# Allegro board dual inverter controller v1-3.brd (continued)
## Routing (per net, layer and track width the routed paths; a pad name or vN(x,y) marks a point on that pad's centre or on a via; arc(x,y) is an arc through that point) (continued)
1: length 124.9
  TOP w0.381: DT9.3 v1(220.56,97.14) ; LT27.2 220.22,103.26 CT154.2 v1(221.69,103.12) ; UT38.15 214.77,99.37 215.22,99.82 CT155.2 CT151.2 v1(218.69,99.82) ; UT38.11 214.36,94.29 214.74,93.91 v1(214.74,93.63) 215.08,93.29 RT228.2
  GND1 w0.381: JT3.11 231.36,112.5 ; JT3.11 228.85,115.02 ; JT3.11 226.99,114.36 ; JT3.11 228.85,109.99 ; JT3.11 226.33,112.5 ; JT3.11 230.7,114.36 ; JT3.11 230.7,110.65 ; JT3.11 226.99,110.65 ; 226.99,85.66 JT3.10 ; JT3.10 228.85,90.03 ; JT3.10 230.7,89.37 ; JT3.10 226.33,87.51 ; JT3.10 228.85,85 ; JT3.10 231.36,87.51 ; JT3.10 226.99,89.37 ; JT3.10 230.7,85.66 ; JT3.3 228.14,99.29 ; JT3.3 226.71,99.29 ; JT3.3 227.43,99.11 ; JT3.3 228.33,100.01 ; JT3.3 226.71,100.72 ; JT3.3 227.43,100.91 ; JT3.3 228.14,100.72 ; JT3.3 226.52,100.01 ; 227.43,104.65 JT3.5 ; JT3.5 228.14,106.26 ; JT3.5 228.14,104.83 ; JT3.5 227.43,106.45 ; JT3.5 228.33,105.55 ; JT3.5 226.71,106.26 ; JT3.5 226.71,104.83 ; JT3.5 226.52,105.55
  PWR2 w0.381: JT3.11 230.7,110.65 ; JT3.11 226.33,112.5 ; JT3.11 226.99,110.65 ; JT3.11 231.36,112.5 ; JT3.11 228.85,109.99 ; JT3.11 230.7,114.36 ; JT3.11 228.85,115.02 ; JT3.11 226.99,114.36 ; JT3.10 231.36,87.51 ; JT3.10 228.85,90.03 ; JT3.10 226.99,85.66 ; JT3.10 226.99,89.37 ; JT3.10 230.7,89.37 ; JT3.10 226.33,87.51 ; JT3.10 230.7,85.66 ; JT3.10 228.85,85 ; 227.43,104.65 JT3.5 ; JT3.5 228.33,105.55 ; JT3.5 226.71,106.26 ; JT3.5 227.43,106.45 ; JT3.5 228.14,106.26 ; JT3.5 226.52,105.55 ; JT3.5 228.14,104.83 ; JT3.5 226.71,104.83 ; JT3.3 228.33,100.01 ; JT3.3 226.71,99.29 ; JT3.3 226.52,100.01 ; JT3.3 227.43,100.91 ; JT3.3 226.71,100.72 ; JT3.3 228.14,100.72 ; JT3.3 228.14,99.29 ; JT3.3 227.43,99.11
CANA-H: length 18
  TOP w0.381: JT3.7 226.65,98.62 225.44,97.4 222.46,97.4 221.79,98.08 DT9.1 218.18,98.08 RT224.1 217.23,97.94 216.71,97.42 216.17,97.42 215.84,97.75 215.1,97.75 214.74,98.1 UT38.14
CANA-L: length 14.9
  TOP w0.381: JT3.2 226.28,97.24 225.89,96.85 222.46,96.85 221.82,96.2 DT9.2 218.18,96.2 RT224.2 217.23,96.34 216.71,96.86 215.94,96.86 215.61,97.19 215.1,97.19 214.74,96.83 UT38.13
CANA-RX: length 109.9
  TOP w0.381: v1(172.04,102.97) 171.6,102.53 171.6,100.78 121.24,50.43 121.24,49.34 120.83,48.92 JT26.80 ; UT38.5 197.16,100.64 194.65,103.16 190.18,103.16 190.17,103.17 v1(189.35,103.17)
  BOTTOM w0.381: v1(172.04,102.97) 172.24,103.17 v1(189.35,103.17)
CANA-TX: length 109.3
  TOP w0.381: v1(172.59,102.41) 172.59,100.96 121.83,50.2 121.83,49.13 121.64,48.94 JT26.82 ; v1(189.35,102.38) 190.17,102.38 190.18,102.4 194.35,102.4 198.64,98.1 UT38.7
  BOTTOM w0.381: v1(172.59,102.41) 188.65,102.41 188.68,102.38 v1(189.35,102.38)
CASE-TEMP: length 58.3
  TOP w0.381: JT26.30 97.64,50.31 92.44,55.51 90.92,55.51 87.28,59.14 v1(86.19,59.14)
  LAYER3 w0.381: v1(77.12,91.73) 77.12,76.82 81.34,72.6 81.34,64.61 86.19,59.76 v1(86.19,59.14)
  BOTTOM w0.381: RB26.2 CB11.1 77.12,92.45 77.12,92.45 v1(77.12,91.73)
COS-A: length 111.5
  TOP w0.381: JT26.36 100.02,54.48 101.73,56.19 v1(103.09,56.19) ; CT54.1 JT20.1
  TOP w0.508: CT54.1 RT99.2
  LAYER3 w0.381: JT20.1 187.57,70.2 184.31,66.94 184.31,62.49 178.01,56.19 v1(103.09,56.19)
COS-A-N: length 23.8
  TOP w0.381: JT18.6 225.39,74.66 224.22,74.66 220.13,70.57 218.14,70.57 217.17,69.6 215.24,69.6 214.64,70.2 DT13.3 213.9,70.2 213.87,70.18 213.32,70.18 212.92,70.57 210.04,70.57 209.52,70.05 RT95.1
  TOP w0.508: RT95.1 CT53.1 207.16,70.07 RT96.1
COS-A-P: length 23.8
  TOP w0.381: JT18.5 225.24,75.22 223.99,75.22 219.9,71.13 218.2,71.13 217.81,71.52 217.1,71.52 217.08,71.5 DT13.6 215.95,72.11 213.9,72.11 212.92,71.13 210.04,71.13 209.52,71.65 RT95.2
  TOP w0.508: RT93.1 207.1,71.57 CT53.2 RT95.2
COS-B: length 99.9
  TOP w0.381: v1(103.18,54.46) 102.45,53.73 102.45,48.66 102.44,48.65 JT26.42 ; CT72.1 JT27.1
  TOP w0.508: CT72.1 RT121.2
  LAYER3 w0.381: JT27.1 179.38,55.17 178.67,54.45 156.34,54.45 156.19,54.6 103.94,54.6 103.8,54.46 v1(103.18,54.46)
COS-B-N: length 23.2
  TOP w0.381: RT117.1 209.52,55.02 210.04,55.54 212.86,55.54 213.25,55.15 213.87,55.15 213.89,55.17 DT10.3 215.13,55.17 215.69,54.61 217.12,54.61 217.81,55.29 219.33,55.29 222.26,58.23 225.32,58.23 JT22.6
  TOP w0.508: RT119.1 207.16,55.04 CT71.1 RT117.1
COS-B-P: length 23.2
  TOP w0.381: JT22.5 225.32,58.78 222.03,58.78 219.34,56.1 218.19,56.1 217.79,56.49 217.1,56.49 217.08,56.47 DT10.6 216.34,56.47 215.78,57.03 213.79,57.03 212.86,56.1 210.04,56.1 209.52,56.62 RT117.2
  TOP w0.508: RT115.1 207.1,56.54 CT71.2 RT117.2
CURRENT-U: length 90
  TOP w0.381: v1(90.41,48.78) 90.42,48.77 JT26.12 ; JT11.1 127.85,110.63 127.9,110.68 RT50.2
  LAYER3 w0.508: v1(90.41,48.78) 90.41,51.08 100.05,60.71 110.55,60.71 127.85,78.01 JT11.1
  BOTTOM w0.381: CB55.1 87.01,51 88.56,49.45 89.96,49.45 90.41,49 v1(90.41,48.78)
CURRENT-U_N: length 63.8
  TOP w0.381: RT4.2 128.68,123.25 RT14.1
  TOP w0.508: 181.45,136.61 177.33,136.61 176.19,137.75 135.53,137.75 129.13,131.35 129.13,126.21 128.68,125.75 RT4.2
CURRENT-U_P: length 61.9
  TOP w0.381: RT15.1 130.28,123.25 RT4.1
  TOP w0.508: RT4.1 130.28,125.75 129.82,126.21 129.82,131.07 135.81,137.06 175.31,137.06 178.91,133.46 178.91,132.8
CURRENT-V: length 94.3
  TOP w0.381: JT4.1 139.96,110.63 140.02,110.68 RT51.2 ; JT26.14 91.24,48.77 v1(91.23,48.78)
  LAYER3 w0.508: v1(91.23,48.78) 91.23,50.35 100.39,59.51 111.47,59.51 139.96,88 JT4.1
  BOTTOM w0.381: v1(91.23,48.78) 91.23,49.4 90.61,50.02 89.74,50.02 88.76,51 CB56.1
CURRENT-V_N: length 52.4
  TOP w0.381: RT5.2 140.84,123.25 RT16.1
  TOP w0.508: RT5.2 141.49,125.47 141.49,131.54 145.18,135.24 172.56,135.24 173.12,134.68 v1(173.57,134.68)
  BOTTOM w0.508: v1(173.57,134.68) 175.42,136.53 179.41,136.53 180.69,135.25 180.69,134.83 JB1.5
CURRENT-V_P: length 47.6
  TOP w0.381: RT17.1 142.44,123.25 RT5.1
  TOP w0.508: RT5.1 142.12,125.14 142.12,125.16 142.17,125.21 142.17,131.26 145.47,134.55 172.27,134.55 172.63,134.19 v1(172.63,133.74)
  BOTTOM w0.508: v1(172.63,133.74) 174.03,133.74 175.62,135.34 178.91,135.34
CURRENT-W: length 98.7
  TOP w0.381: RT52.2 152.19,110.68 152.16,110.65 JT12.1 ; JT26.18 92.84,48.76 v1(92.83,48.77)
  LAYER3 w0.508: JT12.1 152.16,104.25 142.96,95.06 142.96,88.98 112.2,58.23 100.71,58.23 92.83,50.35 v1(92.83,48.77)
  BOTTOM w0.381: CB57.1 90.51,51 91.87,49.64 92.45,49.64 92.83,49.26 v1(92.83,48.77)
CURRENT-W_N: length 33.9
  TOP w0.381: RT18.1 153.01,123.25 RT6.2
  TOP w0.508: JB1.7 178.77,131.53 178.69,131.61 158.22,131.61 153.5,126.89 153.5,125.31 RT6.2
CURRENT-W_P: length 30.5
  TOP w0.381: RT6.1 154.61,123.25 RT19.1
  TOP w0.508: RT6.1 154.19,125.25 154.19,126.6 158.51,130.92 178.41,130.92 178.91,130.41 178.91,130.25
CURRENT-X: length 65.7
  TOP w0.381: JT26.26 96.04,48.76 v1(96.03,48.77)
  TOP w0.508: RT171.2 JT40.1
  LAYER3 w0.508: v1(96.03,48.77) 96.03,48.08 96.88,47.23 106.92,47.23 113.03,41.12 120.17,41.12 120.91,40.37 126.5,40.37 127.52,39.35 143.32,39.35 145.95,36.72 JT40.1
  BOTTOM w0.381: v1(96.03,48.77) 96.03,49.93 95.75,50.21 CB60.1
CURRENT-X_N: length 43.4
  TOP w0.381: JB5.7 153.65,7.12 147.12,13.66 RT213.2 147.12,19.92 RT210.1
CURRENT-X_P: length 42.9
  TOP w0.381: 178.91,5.86 177.76,5.86 177.05,6.57 153.42,6.57 146.56,13.43 146.56,17.46 146.54,17.48 146.52,17.48 146.3,17.69 146.3,18.23 146.18,18.35 RT213.1 145.52,19.92 RT209.1
CURRENT-Y: length 55.4
  TOP w0.381: v1(95.21,48.77) 95.22,48.75 JT26.24
  TOP w0.508: RT170.2 JT39.1
  LAYER3 w0.508: JT39.1 128.75,36.72 126.12,39.35 120.66,39.35 119.66,40.35 112.53,40.35 106.55,46.34 95.77,46.34 95.21,46.9 v1(95.21,48.77)
  BOTTOM w0.381: v1(95.21,48.77) 95.21,49.81 94.02,51 CB59.1
CURRENT-Y_N: length 61.9
  TOP w0.381: RT208.1 134.95,19.92 RT212.2 134.95,16.17 136.79,14.33 138.44,14.33 148.73,4.05 180.6,4.05 183.14,6.59 183.14,7.97 JB5.5
CURRENT-Y_P: length 68.5
  TOP w0.381: RT207.1 133.35,19.92 RT212.1 133.48,18.35 134.35,17.48 134.39,17.48 134.39,15.94 136.56,13.78 138.21,13.78 148.5,3.49 180.84,3.49 183.7,6.36 183.7,9.01 181.78,10.94 178.91,10.94
CURRENT-Z: length 44.7
  TOP w0.381: v1(93.62,48.77) 93.62,48.76 JT26.20
  TOP w0.508: RT169.2 JT38.1
  LAYER3 w0.508: v1(93.62,48.77) 93.62,47.22 95.39,45.45 106.2,45.45 107.16,44.48 107.16,44.47 112.04,39.59 118.52,39.59 121.39,36.72 JT38.1
  BOTTOM w0.381: CB58.1 92.27,51 93.62,49.65 v1(93.62,48.77)
CURRENT-Z_N: length 63.7
  TOP w0.381: v1(136.53,12.02) 136.19,11.67 130.09,11.67 123.86,17.89 123.16,17.89 122.78,18.27 RT211.2 122.78,19.92 RT206.1
  BOTTOM w0.381: JB5.3 178.86,12.2 178.83,12.17 176.03,12.17 175.52,11.67 136.88,11.67 v1(136.53,12.02)
CURRENT-Z_P: length 63.9
  TOP w0.381: v1(136.53,10.76) 136.19,11.11 129.85,11.11 123.63,17.33 122.93,17.33 122.78,17.48 122.18,17.48 121.31,18.35 RT211.1 121.18,19.92 RT205.1 ; 178.91,8.48 JB5.6
  BOTTOM w0.381: JB5.6 176.2,11.11 136.88,11.11 v1(136.53,10.76)
EMUI: length 59.3
  TOP w0.381: JT17.14 67.45,88.38 65.95,86.88 65.95,71.47 68,69.43 74.08,69.43 75.23,68.28 75.23,65.07 77.71,62.59 77.71,51.54 79.86,49.39 84.26,49.39 85.33,48.32 85.33,46.19 85.87,45.65 JT26.1
EMUO: length 58.6
  TOP w0.381: JT26.2 86.44,48.65 85.07,50.02 80.12,50.02 78.34,51.8 78.34,62.85 75.86,65.33 75.86,68.54 74.34,70.06 68.26,70.06 66.58,71.74 66.58,86.34 67.4,87.16 69.78,87.16 JT17.13
EXC-A-N: length 60.5
  TOP w0.254: CT158.2 RT233.2 216.26,36.21 UT41.9
  TOP w0.381: DT15.3 238.5,74.43 237.42,74.43 236.9,74.95 232.59,74.95 JT18.2 ; CT158.2 219.35,36 v1(219.6,36.25)
  LAYER3 w0.381: JT18.2 231.39,72.57 234.5,69.46 234.5,56.83 228.26,50.59 223.96,50.59 221.86,48.49 221.86,40.23 220.24,38.61 220.24,36.89 v1(219.6,36.25)
EXC-A-P: length 63.1
  TOP w0.254: CT157.2 RT230.2 216.27,38.81 UT41.13
  TOP w0.381: JT18.1 232.16,75.51 237.16,75.51 237.96,76.31 240.1,76.31 DT15.6 ; CT157.2 219.36,39.02 v1(219.6,39.26)
  LAYER3 w0.381: JT18.1 230.13,75.03 230.13,73.04 233.94,69.23 233.94,57.06 228.03,51.15 223.73,51.15 221.3,48.72 221.3,40.46 220.1,39.26 v1(219.6,39.26)
EXC-B-N: length 32.1
  TOP w0.254: CT166.2 RT244.2 216.47,44.87 UT43.9
  TOP w0.381: v1(219.73,44.67) CT166.2 ; JT22.2 232.53,57.23 233.52,58.23 236.64,58.23 237.09,57.77 238.11,57.77 238.13,57.79 DT12.3
  LAYER3 w0.381: JT22.2 231.39,56.81 226.55,51.97 223.03,51.97 220.57,49.51 220.57,45.51 v1(219.73,44.67)
EXC-B-P: length 34.1
  TOP w0.254: UT43.13 216.47,47.47 RT237.2 CT162.2
  TOP w0.381: JT22.1 232.53,59.77 233.52,58.78 236.58,58.78 237.45,59.65 239.73,59.65 240.29,59.09 DT12.6 ; CT162.2 219.61,47.69 v1(219.9,47.97)
  LAYER3 w0.381: v1(219.9,47.97) 219.88,47.99 219.88,49.62 222.79,52.53 226.32,52.53 230.14,56.35 230.14,58.53 JT22.1
GLOBAL-FAULT-ALL: length 64.5
  TOP w0.381: v1(160.72,59.19) 161.66,59.19 162.7,58.14 JT26.134 ; v1(168.16,78.19) 168.16,80.5 173.82,86.17 185.25,86.17 187.46,83.96 JT16.1
  LAYER3 w0.381: v1(168.16,78.19) 168.16,66.01 161.34,59.19 v1(160.72,59.19)
  BOTTOM w0.381: UB17.4 159.6,60.31 v1(160.72,59.19)
GLOBAL-FAULT-UVW: length 22.7
  TOP w0.381: JT26.130 v1(161.1,57.69)
  BOTTOM w0.381: UB15.4 159.6,63.76 ; 159.6,63.76 160.13,64.29 161.76,64.29 162.8,63.25 162.8,59.38 v1(161.1,57.69) ; 159.6,63.76 UB17.3
GLOBAL-FAULT-XYZ: length 26.4
  TOP w0.381: JT26.132 161.91,47.67 v1(161.91,48.83) 161.91,57.98 161.53,58.36 v1(160.59,58.36)
  BOTTOM w0.381: UB17.6 157.69,59.99 159.32,58.36 v1(160.59,58.36) ; UB20.4 159.06,40.69 159.8,41.42 159.8,46.72 v1(161.91,48.83)
I2CA-SCL: length 91.2
  TOP w0.381: v1(124.03,44.4) JT26.87 ; v1(124,49.2) 124,50.01 175.51,101.52 175.51,106 175.64,106.12 RT54.1 175.64,107.76 175.3,108.1 JT2.9
  BOTTOM w0.381: v1(124.03,44.4) 124.03,45.02 124,45.05 v1(124,49.2)
I2CA-SDA: length 93.9
  TOP w0.381: v1(123.29,49.6) 123.29,50.22 172.88,99.82 173.02,99.82 173.5,100.3 RT53.1 173.5,107.95 174.04,108.48 174.04,114.12 JT2.10 ; JT26.85 v1(123.24,44.4)
  BOTTOM w0.381: v1(123.29,49.6) 123.24,49.55 v1(123.24,44.4)
LED-G: length 20
  TOP w0.381: v1(163.61,43.39) 162.7,44.3 JT26.133 ; RT154.1 v1(178.34,39.51)
  BOTTOM w0.381: v1(163.61,43.39) 165.32,41.69 176.15,41.69 v1(178.34,39.51)
LED-R: length 16.5
  TOP w0.381: RT152.1 v1(172.88,39.51) ; JT26.129 161.1,43.64 v1(162.48,42.26)
  BOTTOM w0.381: v1(162.48,42.26) 164.65,40.09 172.29,40.09 v1(172.88,39.51)
LED-Y: length 18.3
  TOP w0.381: JT26.131 161.92,43.98 v1(163.06,42.84) ; RT153.1 v1(175.61,39.51)
  BOTTOM w0.381: v1(175.61,39.51) 174.21,40.9 164.99,40.9 v1(163.06,42.84)
PWM7A: length 116.5
  TOP w0.381: JT26.58 112.04,54.17 119.14,61.27 124.28,61.27 160.46,97.45 160.46,116.72 164.65,120.91 v1(177.28,120.91)
  LAYER3 w0.381: v1(177.28,120.91) 177.84,120.35 JT2.12
PWM7B: length 116.5
  TOP w0.381: v1(176.57,119.92) 175.94,119.92 175.59,120.28 164.92,120.28 161.09,116.46 161.09,97.19 124.55,60.64 119.62,60.64 112.83,53.85 JT26.60
  LAYER3 w0.381: JT2.11 176.58,114.09 176.58,119.03 176.57,119.05 v1(176.57,119.92)
PWM8A: length 113.7
  TOP w0.381: JT2.14 180.38,117.31 178.66,119.02 164.56,119.02 161.73,116.19 161.73,96.92 124.78,59.98 120.11,59.98 113.64,53.51 JT26.62
PWM8B: length 113.9
  TOP w0.381: JT26.64 114.43,53.22 120.48,59.28 124.98,59.28 162.36,96.66 162.36,115.93 164.82,118.39 177.94,118.39 179.09,117.24 179.09,114.12 JT2.13
PWM9A: length 55.2
  TOP w0.381: RT66.1 v1(183.54,93.72) ; v1(176.32,50.12) 176.32,74.46 182.25,80.4 v1(182.28,80.4) ; JT26.167 v1(176.32,44.29)
  BOTTOM w0.381: v1(183.54,93.72) 182.28,92.46 v1(182.28,80.4) ; v1(176.32,50.12) v1(176.32,44.29)
PWM9B: length 44.7
  TOP w0.381: RT75.1 184.13,87.85 183.96,87.69 v1(183.3,87.69) ; JT26.168 176.32,49.01 177.07,49.77 177.07,74.02 182.74,79.69 182.84,79.69 v1(183.3,80.15)
  BOTTOM w0.381: v1(183.3,80.15) v1(183.3,87.69)
QEA_A: length 71.5
  TOP w0.381: v1(119.4,51.45) 118.76,50.81 118.35,50.81 118.35,50.81 117.64,50.81 116.03,49.2 JT26.68
  BOTTOM w0.381: UB22.3 169.97,31.11 167.49,33.58 155.74,33.58 149.18,40.14 123.63,40.14 119.03,44.74 119.03,51.09 v1(119.4,51.45)
QEA_B: length 68.9
  TOP w0.381: v1(119.9,50.63) 119.27,50 117.98,50 116.84,48.86 JT26.70
  BOTTOM w0.381: v1(119.9,50.63) 119.9,50.25 119.71,50.06 119.71,50.05 119.59,49.92 119.59,44.97 123.86,40.7 149.41,40.7 155.88,34.23 167.76,34.23 170.24,31.76 UB22.4
QEA_I: length 65.4
  TOP w0.381: JT26.74 118.44,48.65 118.93,49.14 119.75,49.14 v1(120.39,49.78)
  BOTTOM w0.381: UB22.5 170.5,32.41 168.03,34.88 156.02,34.88 149.64,41.26 124.1,41.26 120.15,45.2 120.15,48.92 120.39,49.16 v1(120.39,49.78)
QEB_A: length 56.5
  TOP w0.381: v1(147.58,50.78) 131.02,50.78 128.83,48.59 JT26.100
  BOTTOM w0.381: v1(147.58,50.78) 147.58,44.11 156.16,35.53 168.3,35.53 170.77,33.06 UB22.6
QEB_B: length 54.2
  TOP w0.381: JT26.102 129.64,48.32 131.43,50.11 v1(148.26,50.11)
  BOTTOM w0.381: UB22.7 171.04,33.71 168.57,36.18 156.41,36.18 148.22,44.37 148.22,49.4 148.26,49.44 v1(148.26,50.11)
QEB_I: length 51.4
  TOP w0.381: v1(148.93,49.44) 133.92,49.44 133.91,49.45 132.04,49.45 131.24,48.65 JT26.106
  BOTTOM w0.381: UB22.8 171.31,34.36 168.84,36.83 156.66,36.83 148.85,44.63 148.85,48.69 148.93,48.76 v1(148.93,49.44)
QEPA-A-IN: length 20.2
  TOP w0.381: RT186.2 CT118.1 191.13,27.53 190.43,26.83 JT41.1
  BOTTOM w0.381: UB22.21 179,31.76 181.32,29.45 181.32,27.24 183.12,25.43 185.25,25.43 JT41.1
QEPA-B-IN: length 20.9
  TOP w0.381: CT131.1 RT194.2 191.15,24.27 191.1,24.21 185.18,24.21 184.11,25.28 JT41.2
  BOTTOM w0.381: UB22.20 179.27,32.41 181.97,29.72 181.97,27.77 182.9,26.83 JT41.2
QEPA-I-IN: length 18.6
  TOP w0.381: JT41.3 190.91,29.37 191.13,29.15 CT116.1 RT172.2
  BOTTOM w0.381: JT41.3 185.39,28.11 183.59,28.11 182.62,29.09 182.62,29.99 179.54,33.06 UB22.19
QEPB-A-IN: length 17
  TOP w0.381: CT106.1 RT166.2 191.15,32.41 190.38,33.18 185.38,33.18 JT41.6
  BOTTOM w0.381: JT41.6 182.61,31.91 180.81,33.71 UB22.18
QEPB-B-IN: length 17
  TOP w0.381: RT156.2 CT99.1 190.58,35.66 189.37,34.45 JT41.7
  BOTTOM w0.381: JT41.7 185.39,33.19 182.25,33.19 181.08,34.36 UB22.17
QEPB-I-IN: length 17.5
  TOP w0.381: CT91.1 RT148.2 191.15,38.91 187.95,35.71 185.37,35.71 JT41.8
  BOTTOM w0.381: JT41.8 181.91,34.45 181.35,35.01 UB22.16
RSLV-A-PWM: length 17
  TOP w0.381: JT26.169 177.1,44.64 178.2,43.54 181.85,43.54 182.48,44.17 188.19,44.17 189.25,45.23 RT163.1
RSLV-B-PWM: length 16.7
  TOP w0.381: JT26.170 177.1,48.68 179.16,50.74 RT242.1
SD-C1: length 91.8
  TOP w0.381: JT2.15 182.92,106.2 129.64,52.93 v1(129.64,52.92) ; JT26.101 v1(129.64,44.38)
  BOTTOM w0.381: v1(129.64,44.38) v1(129.64,52.92)
SD-C2: length 92.2
  TOP w0.381: JT2.17 185.46,106.48 131.24,52.26 v1(131.24,52.25) ; JT26.105 v1(131.24,44.38)
  BOTTOM w0.381: v1(131.24,44.38) v1(131.24,52.25)
SD-C3: length 92.6
  TOP w0.381: JT2.19 188,106.76 132.84,51.6 v1(132.84,51.6) ; JT26.109 v1(132.84,44.38)
  BOTTOM w0.381: v1(132.84,44.38) v1(132.84,51.6)
SD-D1: length 94.7
  TOP w0.381: JT2.16 182.92,114.61 181.66,113.36 181.66,106.09 128.83,53.26 v1(128.83,53.25) ; JT26.99 v1(128.83,44.38)
  BOTTOM w0.381: v1(128.83,44.38) v1(128.83,53.25)
SD-D2: length 95.1
  TOP w0.381: JT26.103 v1(130.43,44.38) ; v1(130.43,52.59) 130.43,52.6 184.2,106.37 184.2,114.12 JT2.18
  BOTTOM w0.381: v1(130.43,44.38) v1(130.43,52.59)
SD-D3: length 95.4
  TOP w0.381: JT26.107 v1(132.03,44.38) ; v1(132.03,51.93) 132.03,51.94 186.74,106.65 186.74,114.12 JT2.20
  BOTTOM w0.381: v1(132.03,44.38) v1(132.03,51.93)
SHUTDOWN+15V: length 59
  TOP w0.381: v1(220.16,34.57) 221.44,34.57 RT160.1 RT161.1 ; JT26.155 171.46,45.6 v1(171.46,44.23)
  LAYER3 w0.381: v1(175.32,42.91) 185.5,42.91 195.8,32.6 218.2,32.6 v1(220.16,34.57)
  BOTTOM w0.381: v1(175.32,42.91) 172.02,42.91 171.46,43.47 v1(171.46,44.23)
SIN-A: length 119.3
  TOP w0.381: CT45.1 JT19.1 ; JT26.34 99.24,54.66 101.55,56.97 v1(103.03,56.97)
  TOP w0.508: CT45.1 RT83.2
  LAYER3 w0.381: JT19.1 187.47,77.71 183.5,73.74 183.5,62.82 177.65,56.97 v1(103.03,56.97)
SIN-A-N: length 27.3
  TOP w0.381: RT80.1 209.52,77.56 210.04,78.09 212.82,78.09 213.22,77.69 214.4,77.69 DT14.3 215.03,77.1 217.22,77.1 218.2,78.09 226.76,78.09 227.58,77.26 227.58,75.01 JT18.4
  TOP w0.508: RT80.1 CT44.1 207.16,77.59 RT81.1
SIN-A-P: length 25.5
  TOP w0.381: RT80.2 209.52,79.16 210.04,78.64 212.84,78.64 213.77,79.57 215.4,79.57 215.96,79.01 DT14.6 217.11,79.01 217.14,79.04 217.69,79.04 218.09,78.64 226.99,78.64 228.85,76.79 JT18.3
  TOP w0.508: RT80.2 CT44.2 207.1,79.09 RT79.1
SIN-B: length 104.2
  TOP w0.381: v1(103.18,55.41) 102.56,55.41 101.62,54.47 JT26.40 ; CT63.1 JT23.1
  TOP w0.508: CT63.1 RT105.2
  LAYER3 w0.381: v1(103.18,55.41) 115.5,55.41 115.52,55.43 178.53,55.43 185.78,62.68 JT23.1
SIN-B-N: length 28.1
  TOP w0.381: RT102.1 209.52,62.53 210.04,63.05 212.78,63.05 213.18,62.66 213.87,62.66 213.9,62.68 DT11.3 214.64,62.68 215.2,62.12 217.23,62.12 218.18,63.08 225.58,63.08 227.5,61.16 227.5,58.58 JT22.4
  TOP w0.508: RT102.1 CT61.1 207.16,62.56 RT103.1
SIN-B-P: length 26.5
  TOP w0.381: JT22.3 228.85,60.61 225.81,63.64 218.12,63.64 217.69,64.07 216.64,64.07 DT11.6 216.55,64.18 216.08,64.65 213.82,64.65 212.78,63.61 210.04,63.61 209.52,64.13 RT102.2
  TOP w0.508: RT102.2 CT61.2 207.1,64.06 RT101.1
SPIA-CLK: length 97.7
  TOP w0.381: JT26.71 v1(117.63,44.38) ; JT2.6 171.47,114.12 171.47,111.3 168.34,108.16 168.34,99.29 121.78,52.73 117.83,52.73 v1(117.26,52.16)
  BOTTOM w0.381: v1(117.26,52.16) 117.26,45.37 117.63,45 v1(117.63,44.38)
SPIA-MISO: length 94.8
  TOP w0.381: JT26.69 v1(116.84,44.38) ; JT2.5 170.22,111.63 167.78,109.19 167.78,99.59 121.53,53.34 116.98,53.34 v1(116.47,52.83)
  BOTTOM w0.381: v1(116.84,44.38) 116.7,44.52 116.7,44.66 116.47,44.89 v1(116.47,52.83)
SPIA-MOSI: length 94.5
  TOP w0.381: JT2.3 167.68,111.41 166.87,110.61 166.87,99.5 121.32,53.94 116.1,53.94 v1(115.66,53.5) ; JT26.67 v1(116.03,44.38)
  BOTTOM w0.381: v1(116.03,44.38) 115.66,44.75 v1(115.66,53.5)
SPIA-STE: length 96
  TOP w0.381: JT26.73 v1(118.44,44.38) ; v1(118.07,51.48) 118.76,52.17 122.01,52.17 168.89,99.06 168.89,99.11 169.04,99.25 v1(169.04,107.81)
  BOTTOM w0.381: JT2.4 168.93,114.12 168.93,109.88 168.98,109.83 168.98,108.48 169.04,108.43 v1(169.04,107.81) ; v1(118.07,51.48) 118.07,45.37 118.44,45 v1(118.44,44.38)
TCK: length 54.6
  TOP w0.381: JT26.5 88.04,44.19 87.46,43.62 84.92,43.62 83.6,44.94 83.6,47 82.46,48.14 79.31,48.14 76.44,51.01 76.44,62.06 73.72,64.78 v1(73.72,68.61)
  BOTTOM w0.381: v1(73.72,68.61) 73.72,74.48 72.67,75.53 72.67,81.63 JT17.9 JT17.11
TDI: length 38.8
  TOP w0.381: JT26.8 88.82,49.44 86.34,51.93 80.91,51.93 80.25,52.59 80.25,63.64 77.77,66.12 77.77,69.29 72.98,74.07 72.6,74.07 JT17.3
TDO: length 46.9
  TOP w0.381: JT26.6 88.04,49.12 85.86,51.29 80.65,51.29 79.61,52.33 79.61,63.38 77.13,65.86 77.13,69.07 74.87,71.33 70.47,71.33 69.68,72.12 69.68,79.43 JT17.7
TMS: length 40.8
  TOP w0.381: v1(74.39,67.45) 74.39,65 77.07,62.32 77.07,51.27 79.54,48.8 83.93,48.8 84.54,48.19 84.54,45.09 85.35,44.28 86.89,44.28 87.22,44.61 JT26.3
  BOTTOM w0.381: v1(74.39,67.45) 73.72,67.45 72.32,68.84 72.32,71.81 JT17.1
TRST: length 38.9
  TOP w0.381: JT17.2 68.46,72.12 69.89,70.7 74.6,70.7 76.5,68.8 76.5,65.6 78.98,63.11 78.98,52.06 80.38,50.66 85.35,50.66 87.22,48.78 JT26.4
U-FAULT: length 112.3
  TOP w0.381: JT26.122 157.9,57.4 157.69,57.61 v1(157.69,70.32) ; v1(103.77,115.5) 103.17,114.91 UT8.3
  LAYER3 w0.381: v1(103.77,115.5) 112.51,115.5 116.39,111.62 116.39,100.9 v1(114.54,99.04)
  BOTTOM w0.381: v1(114.54,99.04) 114.54,96.5 127.63,83.41 145.22,83.41 157.69,70.94 v1(157.69,70.32) UB15.1
U-FAULT-N: length 46
  TOP w0.381: v1(112.03,132.45) 111.95,132.37 111.95,131.81 111.81,131.68 111.81,131.28 111.7,131.17 111.7,115.3 109.34,112.94 108.57,112.94 107.96,112.33 LT12.1
  BOTTOM w0.381: JB4.8 95.4,139.49 95.4,136.65 99.03,133.02 110.97,133.02 111.54,132.45 v1(112.03,132.45)
U-FAULT-N-FILTER: length 5.4
  TOP w0.381: RT49.2 102.58,112.42 101.9,113.09 101.62,113.09 101.1,113.61 UT8.1
  TOP w0.508: RT49.2 CT27.2 105.33,112.42 LT12.2
U-FAULT-P: length 41.8
  TOP w0.381: v1(111.14,131.56) 111.14,115.53 109.11,113.5 108.57,113.5 107.96,114.11 LT9.1
  BOTTOM w0.381: v1(111.14,131.56) 111.14,132.06 110.74,132.46 98.8,132.46 94.11,137.15 JB4.7
U-FAULT-P-FILTER: length 5
  TOP w0.381: RT49.1 102.38,114.26 UT8.2
  TOP w0.508: RT49.1 CT27.1 104.11,114.11 LT9.2
U-LEN: length 129
  LAYER3 w0.381: v1(118.3,124.91) 115.74,124.91 105.36,135.29 100.49,135.29 100.09,134.9 99.07,134.9 98.67,135.29 87.84,135.29 86.49,136.64 JB4.13
  BOTTOM w0.381: UB18.12 165.1,69.98 147.88,87.2 128.91,87.2 118.26,97.84 118.26,123.92 118.3,123.96 v1(118.3,124.91)
U-LEN-OUT: length 11.9
  TOP w0.381: JT26.144 v1(166.72,48.88)
  BOTTOM w0.381: UB18.8 165.75,53.61 166.72,52.64 v1(166.72,48.88)
U-OCEN: length 130.4
  LAYER3 w0.381: JB4.15 83.95,136.63 85.93,134.66 98.52,134.66 98.84,134.34 100.32,134.34 100.64,134.66 105.09,134.66 115.52,124.24 v1(117.63,124.24)
  BOTTOM w0.381: v1(117.63,124.24) 117.63,118.74 117.61,118.73 117.61,97.57 128.64,86.55 147.61,86.55 164.45,69.71 UB18.11
U-OCEN-OUT: length 11.8
  TOP w0.381: JT26.142 v1(165.9,48.88)
  BOTTOM w0.381: UB18.9 165.1,53.34 165.9,52.53 v1(165.9,48.88)
U-PSDIS: length 127.4
  LAYER3 w0.381: v1(118.97,125.58) 115.97,125.58 105.62,135.93 100.33,135.93 99.86,135.45 99.3,135.45 98.83,135.93 90.13,135.93 89.03,137.02 JB4.11
  BOTTOM w0.381: UB18.13 165.75,70.25 148.15,87.85 129.18,87.85 118.89,98.13 118.89,124.54 118.97,124.63 v1(118.97,125.58)
U-PSDIS-OUT: length 12
  TOP w0.381: JT26.146 v1(167.5,48.88)
  BOTTOM w0.381: v1(167.5,48.88) 167.5,52.77 166.4,53.88 UB18.7
U-RTD: length 106
  TOP w0.381: JT26.92 v1(125.63,48.93) ; UT8.5 101.79,116.21 101.8,116.2 102.06,116.2 v1(102.5,115.76) ; v1(86.52,87.51) 87.49,87.51 92.8,82.2 93.71,82.2 102.5,73.41 107.15,73.41 v1(107.99,72.58)
  LAYER3 w0.381: v1(92.64,103.89) 92.64,112.33 94.27,113.95 94.27,114.08 94.65,114.46 95.81,114.46 97.39,116.05 98.84,116.05 99.13,115.76 v1(102.5,115.76)
  BOTTOM w0.254: UB3.2 84.9,90.37 84.51,89.98 84.51,88.78 85.21,88.08 RB32.1
  BOTTOM w0.381: v1(125.63,48.93) 125.63,50.72 107.99,68.36 v1(107.99,72.58) ; RB32.1 85.55,87.56 86.57,87.56 ; v1(86.52,87.51) 86.57,87.56 ; 86.57,87.56 87.92,88.91 87.92,97.39 92.64,102.12 v1(92.64,103.89)
U-RTD-N: length 42.6
  TOP w0.381: LT3.1 107.96,118.8 108.57,118.19 109.11,118.19 109.49,118.58 109.49,136.63 103.65,142.47 92.28,142.47 91.35,141.53 91.35,140.99 JB4.10
U-RTD-N-FILTER: length 5.5
  TOP w0.381: RT32.2 102.58,118.72 101.9,118.04 101.9,117.99 101.42,117.51 UT8.7
  TOP w0.508: LT3.2 104.11,118.8 CT20.2 RT32.2
U-RTD-P: length 48.5
  TOP w0.381: JB4.9 90.32,139.49 90.32,141.29 92.05,143.03 103.88,143.03 110.05,136.86 110.05,118.34 109.34,117.64 108.57,117.64 107.96,117.03 LT6.1
U-RTD-P-FILTER: length 5
  TOP w0.381: UT8.6 102.37,116.86 RT32.1
  TOP w0.508: RT32.1 CT20.1 104.11,117.03 LT6.2
U-TEMP: length 29.5
  TOP w0.381: JT26.25 96.01,45.63 v1(96.01,44.41)
  BOTTOM w0.381: RB66.2 CB48.1 86.22,61.5 90.77,56.96 95.1,56.96 98.54,53.52 98.54,48.34 96.01,45.82 v1(96.01,44.41)
UHS-PWM: length 113
  TOP w0.381: v1(105.64,44.1) JT26.49 ; RT20.1 v1(105.38,122.07) ; v1(93.74,101.08) 93.74,99.98 94.54,99.18 104.03,99.18 117.35,85.87 117.35,73.89 105.64,62.18 v1(105.64,51.06)
  BOTTOM w0.381: v1(93.74,101.08) 93.74,101.7 95.3,103.26 104.49,103.26 107.4,106.17 JT9.1 107.4,110.65 105.38,112.67 v1(105.38,122.07) ; v1(105.64,51.06) v1(105.64,44.1)
UHS-PWM-N: length 26.1
  TOP w0.381: UT1.3 105.33,125.12 106.44,126.22 106.44,131.81 103.52,134.73 100.97,134.73 v1(99.58,136.13)
  BOTTOM w0.381: JB4.4 100.45,139.51 100.45,137.71 99.7,136.96 99.7,136.25 v1(99.58,136.13)
UHS-PWM-P: length 23.8
  TOP w0.381: JB4.3 99.19,137.65 101.06,135.78 103.25,135.78 106.99,132.04 106.99,125.99 105.52,124.51 101.58,124.51 101.54,124.47 UT1.2
ULS-PWM: length 130.5
  TOP w0.381: v1(106.43,51.06) 106.43,61.86 118.13,73.57 118.13,86.2 104.36,99.97 94.9,99.97 94.52,100.35 v1(94.52,101.08) ; RT3.1 103.9,131.17 v1(103.64,131.43) ; v1(106.43,44.1) JT26.51
  BOTTOM w0.381: v1(106.43,51.06) v1(106.43,44.1) ; v1(103.64,131.43) 109.61,125.46 109.61,116.31 113.5,112.43 JT10.1 113.5,106.17 109.8,102.47 95.92,102.47 v1(94.52,101.08)
ULS-PWM-N: length 25.4
  TOP w0.381: UT1.5 102,126.42 102.05,126.46 104.89,126.46 105.85,127.43 105.85,131.6 103.56,133.89 99.2,133.89 97.91,135.18 97.91,139.51 JB4.6
ULS-PWM-P: length 21.7
  TOP w0.381: UT1.6 102,127.07 102.05,127.02 104.66,127.02 105.29,127.66 105.29,131.37 103.33,133.33 98.97,133.33 96.65,135.64 JB4.5
V-FAULT: length 123.7
  TOP w0.381: UT8.11 93.7,116.86 v1(93.23,116.39) ; JT26.124 158.71,57.74 158.7,57.75 158.7,63.74 159.38,64.42 v1(159.38,70.05)
  LAYER3 w0.381: v1(93.23,116.39) 93.9,117.06 112.75,117.06 117.31,112.5 117.31,100.32 115.8,98.81 115.79,98.81 v1(115.35,98.37)
  BOTTOM w0.381: UB15.3 159.6,69.83 v1(159.38,70.05) 145.21,84.22 127.97,84.22 115.35,96.84 v1(115.35,98.37)
V-FAULT-N: length 41.3
  TOP w0.381: JB3.8 65.55,139.49 65.55,135.74 67.35,133.94 81.37,133.94 85.46,129.86 85.46,119.87 86.36,118.96 86.9,118.96 87.51,119.57 LT1.1
V-FAULT-N-FILTER: length 5.4
  TOP w0.381: RT30.2 92.9,119.48 93.83,118.54 93.86,118.54 94.25,118.16 UT8.9
  TOP w0.508: LT1.2 90.14,119.48 CT18.2 RT30.2
V-FAULT-P: length 39.7
  TOP w0.381: JB3.7 64.61,138.23 64.99,137.85 64.99,135.5 67.11,133.38 81.14,133.38 84.9,129.63 84.9,119.63 86.13,118.4 86.9,118.4 87.51,117.79 LT4.1
V-FAULT-P-FILTER: length 5
  TOP w0.381: RT30.1 93.1,117.62 93.54,117.62 93.65,117.51 UT8.10
  TOP w0.508: LT4.2 90.14,117.88 CT18.1 RT30.1
V-LEN: length 159.2
  LAYER3 w0.381: v1(120.24,122.58) 115.38,122.58 104.57,133.39 100.96,133.39 100.78,133.22 82.67,133.22 81.1,134.79 58.5,134.79 56.65,136.64 JB3.13
  BOTTOM w0.381: UB18.15 167.05,70.79 148.69,89.15 129.71,89.15 120.21,98.65 120.21,121.6 120.24,121.62 v1(120.24,122.58)
V-LEN-OUT: length 12.4
  TOP w0.381: JT26.152 v1(169.92,48.88)
  BOTTOM w0.381: v1(169.92,48.88) 169.92,52.23 167.7,54.45 UB18.5
V-OCEN: length 160.7
  LAYER3 w0.381: v1(119.56,121.9) 115.16,121.9 104.31,132.76 101.11,132.76 101.01,132.66 82.33,132.66 80.83,134.15 56.47,134.15 54.11,136.51 JB3.15
  BOTTOM w0.381: UB18.14 166.4,70.52 148.42,88.5 129.45,88.5 119.56,98.38 v1(119.56,121.9)
V-OCEN-OUT: length 12.3
  TOP w0.381: JT26.150 v1(169.1,48.88)
  BOTTOM w0.381: UB18.6 167.05,54.18 169.1,52.12 v1(169.1,48.88)
V-PSDIS: length 157.8
  LAYER3 w0.381: v1(120.91,123.25) 115.61,123.25 104.83,134.03 100.8,134.03 100.55,133.78 98.6,133.78 98.36,134.03 82.76,134.03 81.36,135.42 60.4,135.42 59.19,136.64 JB3.11
  BOTTOM w0.381: UB18.16 167.7,71.06 148.96,89.8 129.98,89.8 120.86,98.92 120.86,122.25 120.91,122.3 v1(120.91,123.25)
V-PSDIS-OUT: length 12.5
  TOP w0.381: JT26.154 v1(170.7,48.88)
  BOTTOM w0.381: UB18.4 168.35,54.72 170.7,52.36 v1(170.7,48.88)
V-RTD: length 93.3
  TOP w0.381: v1(96.66,86.9) 96.66,82.3 104.85,74.1 107.9,74.1 108.8,73.2 v1(108.8,72.58) ; JT26.94 v1(126.44,48.93) ; UT8.13 92.54,115.56 v1(91.96,116.14)
  LAYER3 w0.381: v1(96.66,86.9) 94.02,89.54 94.02,93.2 91.96,95.26 v1(91.96,116.14)
  BOTTOM w0.254: RB33.1 95.39,88.08 94.68,88.78 94.68,89.98 95.07,90.37 UB4.2
  BOTTOM w0.381: v1(96.66,86.9) 96.66,87.52 96.28,87.9 RB33.1 ; v1(126.44,48.93) 126.44,51.05 108.8,68.7 v1(108.8,72.58)
V-RTD-N: length 49.8
  TOP w0.381: LT11.1 87.39,112.96 86.78,113.57 86.01,113.57 83.78,115.8 83.78,129.16 80.68,132.27 65.06,132.27 61.17,136.15 61.17,137.01 60.47,137.71 60.47,139.51 JB3.10
V-RTD-N-FILTER: length 5.5
  TOP w0.381: RT48.2 92.77,113.05 93.44,113.73 93.44,113.78 93.93,114.26 UT8.15
  TOP w0.508: LT11.2 90.01,113.05 CT26.2 RT48.2
V-RTD-P: length 45.6
  TOP w0.381: JB3.9 61.73,136.38 65.29,132.82 80.91,132.82 84.34,129.4 84.34,116.03 86.24,114.13 86.78,114.13 87.39,114.74 LT8.1
V-RTD-P-FILTER: length 5
  TOP w0.381: RT48.1 93.28,114.65 93.54,114.91 UT8.14
  TOP w0.508: LT8.2 90.01,114.65 CT26.1 RT48.1
V-TEMP: length 27
  TOP w0.381: v1(96.82,44.41) JT26.27
  BOTTOM w0.381: v1(96.82,44.41) 96.82,45.48 99.12,47.78 99.12,54.09 95.18,58.02 92.9,58.02 89.52,61.4 89.52,61.48 89.47,61.53 RB67.2 CB49.1
V_U+: length 6.1
  TOP w0.635: RT55.1 JT43.12
V_U-: length 6.1
  BOTTOM w0.635: RB19.1 JT43.11
V_V+: length 6.1
  TOP w0.635: RT67.1 JT43.10
V_V-: length 6.1
  BOTTOM w0.635: RB41.1 JT43.9
V_W+: length 6.1
  TOP w0.635: RT84.1 JT43.8
V_W-: length 6.1
  BOTTOM w0.635: RB59.1 JT43.7
V_X+: length 6.1
  TOP w0.635: RT106.1 JT43.6
V_X-: length 6.1
  BOTTOM w0.635: RB74.1 JT43.5
V_Y+: length 6.1
  TOP w0.635: RT130.1 JT43.4
V_Y-: length 6.1
  BOTTOM w0.635: RB83.1 JT43.3
V_Z+: length 6.1
  TOP w0.635: RT174.1 JT43.2
V_Z-: length 6.1
  BOTTOM w0.635: JT43.1 RB103.1
VDC-M: length 2.9
  TOP w0.635: 14.36,116.19 13.34,116.19 13.34,116.19 JT1.2
VDC-P: length 2.9
  TOP w0.635: JT1.1 14.36,124.19
VHS-PWM: length 112.5
  TOP w0.381: RT2.1 91.06,129.78 v1(90.05,129.78) ; JT26.53 107.24,44.51 107.59,44.15 108.62,44.15 109.79,45.32 109.79,49.82 v1(109.56,50.05) ; JT7.1 95.21,104.98 99.25,100.95 104.53,100.95 118.95,86.53 118.95,73.23 107.24,61.52 107.24,50.36 v1(107.55,50.05)
  BOTTOM w0.381: v1(90.05,129.78) 90.05,116.7 95.21,111.54 JT7.1 ; v1(109.56,50.05) v1(107.55,50.05)
VHS-PWM-N: length 35.3
  TOP w0.381: v1(69.86,136.51) 70.42,135.95 82.46,135.95 87.34,131.07 87.34,128.91 89.13,127.11 93.35,127.11 93.4,127.07 UT1.11
  BOTTOM w0.381: v1(69.86,136.51) 70.24,136.89 70.24,137.34 70.61,137.71 70.61,139.51 JB3.4
VHS-PWM-P: length 31.2
  TOP w0.381: JB3.3 71.07,136.51 82.69,136.51 87.89,131.3 87.89,129.14 89.36,127.67 93.35,127.67 93.4,127.72 UT1.10
VLS-PWM: length 95.5
  TOP w0.381: RT13.1 v1(91.48,121.37) ; JT8.1 101.31,105.28 119.73,86.86 119.73,72.9 108.03,61.19 108.03,50.64 108.89,49.78 108.89,45.95 108.59,45.65 JT26.55
  BOTTOM w0.381: v1(91.48,121.37) 95.13,117.71 95.13,113.65 98.18,110.6 99.9,110.6 101.31,109.19 JT8.1
VLS-PWM-N: length 37.4
  TOP w0.381: UT1.13 93.4,125.77 93.35,125.72 88.77,125.72 86.57,127.92 86.57,130.32 81.83,135.06 69.66,135.06 68.07,136.65 68.07,139.51 JB3.6
VLS-PWM-P: length 35.5
  TOP w0.381: UT1.14 93.4,125.12 93.35,125.16 88.54,125.16 86.01,127.69 86.01,130.09 81.6,134.5 69.43,134.5 66.81,137.12 JB3.5
VSENSE-DC: length 46.8
  TOP w0.381: v1(87.49,57.39) 89.93,54.95 89.93,52.18 91.96,50.15 96.06,50.15 96.82,49.39 v1(96.82,48.77) 96.82,48.76 JT26.28
  LAYER3 w0.381: JT21.1 72.15,66.53 73.11,65.57 73.11,59.93 75.65,57.39 v1(87.49,57.39)
  BOTTOM w0.381: CB61.1 97.51,50.07 96.82,49.39 v1(96.82,48.77) ; RB65.2 JT21.1
VSENSE-U: length 40.6
  TOP w0.381: v1(89.61,44.36) 89.61,45.63 JT26.9
  LAYER3 w0.381: JT24.1 71.77,61.58 72.3,61.04 72.3,58.76 74.94,56.12 74.94,50.58 80.15,45.37 89.22,45.37 89.61,44.98 v1(89.61,44.36)
  BOTTOM w0.381: RB72.2 JT24.1 ; v1(89.61,44.36) 89.61,43.73 89.09,43.21 88.16,43.21 87.01,42.06 CB62.1
VSENSE-V: length 36.8
  TOP w0.381: v1(90.4,44.37) 90.4,45.63 JT26.11
  LAYER3 w0.381: JT25.1 71.38,56.62 73.67,54.34 73.67,50.35 80.45,43.57 90.09,43.57 90.4,43.87 v1(90.4,44.37)
  BOTTOM w0.381: CB63.1 88.76,42.06 90.4,43.7 v1(90.4,44.37) ; RB73.2 JT25.1
VSENSE-W: length 34.9
  TOP w0.381: JT26.15 92.05,45.63 v1(92.05,44.38)
  LAYER3 w0.381: v1(92.05,44.38) 92.05,43.47 91.36,42.78 89.59,42.78 89.56,42.76 85.58,42.76 85.55,42.78 80,42.78 71.11,51.67 JT28.1
  BOTTOM w0.381: v1(92.05,44.38) 92.05,43.59 90.51,42.06 CB64.1 ; RB80.2 JT28.1
VSENSE-X: length 34.2
  TOP w0.381: v1(92.84,44.4) JT26.17
  LAYER3 w0.381: JT29.1 73.03,46.72 77.86,41.89 91.74,41.89 92.84,42.99 v1(92.84,44.4)
  BOTTOM w0.381: v1(92.84,44.4) 92.84,42.63 92.27,42.06 CB65.1 ; RB81.2 JT29.1
VSENSE-Y: length 34.5
  TOP w0.381: v1(94.44,44.4) JT26.21
  LAYER3 w0.381: JT30.1 72.4,41.77 73.16,41 92.45,41 94.44,42.99 v1(94.44,44.4)
  BOTTOM w0.381: v1(94.44,44.4) 94.44,43.41 94,42.97 CB66.1 ; RB82.2 JT30.1
VSENSE-Z: length 36.9
  TOP w0.381: v1(95.22,44.38) JT26.23
  LAYER3 w0.381: JT31.1 71.77,36.81 75.19,40.24 92.85,40.24 95.22,42.62 v1(95.22,44.38)
  BOTTOM w0.381: RB89.2 JT31.1 ; CB67.1 95.75,43.23 95.22,43.76 v1(95.22,44.38)
W-FAULT: length 157.9
  TOP w0.381: JT26.126 159.5,63.75 160.27,64.52 v1(160.27,70.23) ; UT4.3 71.7,116.91 v1(71.1,116.31)
  LAYER3 w0.381: v1(116.14,97.7) 116.58,98.14 116.59,98.14 118.35,99.9 118.35,113.6 111.13,120.81 93.36,120.81 93.25,120.7 91.2,120.7 91.08,120.81 74.71,120.81 71.1,117.2 v1(71.1,116.31)
  BOTTOM w0.381: v1(116.14,97.7) 116.14,97.16 128.29,85.01 145.49,85.01 v1(160.27,70.23) 160.27,67.94 160.08,67.75 158.54,67.75 157.69,66.9 UB15.6
W-FAULT-N: length 45.2
  TOP w0.381: LT2.1 66.91,119.49 66.69,119.27 66.15,119.27 51.72,133.7 37.11,133.7 35.19,135.62 35.19,136.51 35.68,137 35.68,139.51 JB2.8
W-FAULT-N-FILTER: length 5.4
  TOP w0.381: UT4.1 73.78,118.21 73.39,118.59 73.11,118.59 72.3,119.4 RT31.2
  TOP w0.508: LT2.2 70.76,119.49 CT19.2 RT31.2
W-FAULT-P: length 43.3
  TOP w0.381: LT5.1 66.91,117.71 51.49,133.14 36.88,133.14 34.63,135.39 34.63,138.02 JB2.7
W-FAULT-P-FILTER: length 5
  TOP w0.381: RT31.1 73.01,117.8 73.25,117.56 UT4.2
  TOP w0.508: RT31.1 CT19.1 70.76,117.71 LT5.2
W-LEN: length 195.3
  LAYER3 w0.381: JB2.13 26.8,135.07 29.05,132.82 80.28,132.82 81.68,131.43 102.69,131.43 103.36,130.75 104.43,130.75 114.88,120.31 121.08,120.31 121.08,120.3 v1(122.26,120.3)
  BOTTOM w0.381: UB19.17 177.06,66.27 152.14,91.19 130.56,91.19 122.26,99.5 122.26,119.35 122.26,119.35 v1(122.26,120.3)
W-LEN-OUT: length 13.1
  TOP w0.381: JT26.162 v1(173.9,48.88)
  BOTTOM w0.381: UB19.3 177.71,58.09 174.99,55.38 174.99,52.12 173.9,51.04 v1(173.9,48.88)
W-OCEN: length 196.3
  LAYER3 w0.381: v1(121.59,119.63) 114.66,119.63 104.09,130.2 103.13,130.2 102.53,130.79 81.42,130.79 80.02,132.19 28.15,132.19 24.26,136.08 JB2.15
  BOTTOM w0.381: v1(121.59,119.63) 121.59,118.75 121.61,118.73 121.61,99.23 130.29,90.54 152,90.54 176.41,66.13 UB19.16
W-OCEN-OUT: length 13.1
  TOP w0.381: JT26.160 v1(173.12,48.88)
  BOTTOM w0.381: v1(173.12,48.88) 173.12,51.17 174.34,52.39 174.34,55.6 177,58.26 177,58.91 177.02,58.93 177.02,59.13 UB19.4
W-PSDIS: length 193.3
  LAYER3 w0.381: v1(122.94,120.98) 115.11,120.98 103.98,132.1 103.36,132.1 103.33,132.06 81.94,132.06 80.55,133.46 31.89,133.46 29.34,136 JB2.11
  BOTTOM w0.381: UB19.18 177.71,66.41 152.28,91.84 130.83,91.84 122.91,99.77 122.91,120 122.94,120.02 v1(122.94,120.98)
W-PSDIS-OUT: length 13
  TOP w0.381: JT26.164 v1(174.72,48.88)
  BOTTOM w0.381: UB19.2 178.36,57.88 175.64,55.17 175.64,51.85 174.72,50.93 v1(174.72,48.88)
W-RTD: length 103.4
  TOP w0.381: UT4.5 75.47,115.61 77.89,113.19 77.89,106.69 80.45,104.12 82.99,104.12 90.79,96.33 100.7,96.33 104.48,92.54 104.48,89.19 v1(106.74,86.93) ; JT26.96 v1(127.23,48.93)
  BOTTOM w0.254: UB5.2 105.24,90.37 104.86,89.98 104.86,88.78 105.56,88.08 RB34.1
  BOTTOM w0.381: RB34.1 106.4,87.9 106.74,87.56 v1(106.74,86.93) 106.74,86.3 106.61,86.18 106.61,76.54 109.59,73.57 109.59,69.02 127.23,51.38 v1(127.23,48.93)
W-RTD-N: length 53.5
  TOP w0.381: JB2.10 30.63,139.51 30.63,136.09 34.76,131.96 50.89,131.96 65.36,117.48 65.36,114.94 66.07,114.23 66.51,114.23 67.08,113.66 67.29,113.66 67.68,113.28 LT10.1
W-RTD-N-FILTER: length 5.4
  TOP w0.381: UT4.7 73.5,114.31 72.3,113.1 RT47.2
  TOP w0.508: RT47.2 CT25.2 70.76,113.01 LT10.2
W-RTD-P: length 48.5
  TOP w0.381: LT7.1 66.3,114.79 65.92,115.17 65.92,117.71 51.12,132.52 34.99,132.52 31.88,135.62 JB2.9
W-RTD-P-FILTER: length 5
  TOP w0.381: UT4.6 72.92,114.96 72.67,114.7 RT47.1
  TOP w0.508: LT7.2 70.76,114.79 CT25.1 RT47.1
W-TEMP: length 24.4
  TOP w0.381: v1(98.44,44.37) 98.42,44.39 JT26.31
  BOTTOM w0.381: RB68.2 CB50.1 92.73,61.5 99.86,54.37 99.86,46.92 98.44,45.51 v1(98.44,44.37)
WHS-PWM: length 118.5
  TOP w0.381: RT1.1 v1(77.1,131.17) ; JT26.50 105.64,48.97 103.89,50.72 103.89,62.72 115.73,74.56 115.73,85.2 103.37,97.57 92.22,97.57 85.76,104.02 85.76,106.44 85.36,106.84 85.36,106.85 84.73,107.48 84.72,107.48 84.52,107.68 JT5.1
  BOTTOM w0.381: JT5.1 79.26,107.68 74.56,112.38 74.56,129.14 74.94,129.52 75.45,129.52 v1(77.1,131.17)
WHS-PWM-N: length 43.6
  TOP w0.381: UT2.3 72.95,126.94 72.86,127.03 60.75,127.03 52.42,135.37 41.03,135.37 v1(39.89,136.51)
  BOTTOM w0.381: JB2.4 40.76,139.51 40.76,137.71 40.51,137.46 40.51,137.13 v1(39.89,136.51)
WHS-PWM-P: length 39.6
  TOP w0.381: UT2.2 60.98,127.59 52.65,135.93 41.26,135.93 40.9,136.29 40.9,136.83 JB2.3
WLS-PWM: length 107.6
  TOP w0.381: RT28.1 78.75,120.76 79.26,121.27 82.43,121.27 82.69,121.01 82.69,114.41 85.73,111.36 87.39,111.36 89.04,109.71 89.04,108.77 89.12,108.69 JT6.1 89.12,101.76 92.55,98.33 103.68,98.33 116.49,85.52 116.49,74.25 104.78,62.54 104.78,50.71 106.43,49.07 JT26.52
WLS-PWM-N: length 46.3
  TOP w0.381: JB2.6 38.22,139.51 38.22,137 37.98,136.76 37.98,135.75 38.92,134.81 52.18,134.81 61.45,125.55 72.86,125.55 72.95,125.64 UT2.5
WLS-PWM-P: length 44.2
  TOP w0.381: JB2.5 37.42,137.77 37.42,135.51 38.68,134.25 51.95,134.25 61.21,124.99 UT2.6
X-FAULT: length 73.6
  TOP w0.381: JT26.121 v1(157.9,43.8) 157.9,41.47 v1(152.19,35.76) ; v1(103.85,19.11) 103.25,18.51 UT35.3
  LAYER3 w0.381: v1(110.68,23.81) 110.68,25.59 119.03,33.94 150.38,33.94 v1(152.19,35.76)
  BOTTOM w0.381: v1(110.68,23.81) 105.97,19.11 v1(103.85,19.11) ; UB20.1 157.16,43.04 157.9,43.78 v1(157.9,43.8)
X-FAULT-N: length 29
  TOP w0.381: JB8.8 90.32,5.49 90.32,7.39 94.39,11.46 106.84,11.46 108.61,13.23 108.61,15.72 107.76,16.57 107.66,16.57 107.27,16.19 LT25.1
X-FAULT-N-FILTER: length 5.4
  TOP w0.381: UT35.1 101.17,17.21 101.69,16.69 101.98,16.69 102.65,16.02 RT216.2
  TOP w0.508: RT216.2 CT144.2 105.41,16.02 LT25.2
X-FAULT-P: length 26.5
  TOP w0.381: LT22.1 107.27,17.51 107.66,17.13 107.99,17.13 109.17,15.95 109.17,13 107.07,10.91 94.62,10.91 91.57,7.85 JB8.7
X-FAULT-P-FILTER: length 5
  TOP w0.381: UT35.2 102.46,17.86 RT216.1
  TOP w0.508: LT22.2 104.19,17.71 CT144.1 RT216.1
X-LEN: length 70.2
  TOP w0.381: UT27.12 155.75,23.39 154.03,21.67 v1(154.03,15.24)
  LAYER3 w0.381: v1(154.03,15.24) 125.17,15.24 123.89,16.52 119.92,16.52 113.05,9.65 102.07,9.65 JB8.13
X-LEN-OUT: length 18.7
  TOP w0.381: UT27.8 156.4,33.02 166.72,43.34 JT26.143
X-OCEN: length 67.6
  TOP w0.381: UT27.11 155.1,23.65 153.35,21.91 v1(153.35,14.51)
  LAYER3 w0.381: v1(153.35,14.51) 125.11,14.51 123.66,15.96 120.32,15.96 113.33,8.97 103.94,8.97 JB8.15
X-OCEN-OUT: length 18.6
  TOP w0.381: JT26.141 165.9,43.34 155.75,33.18 UT27.9
X-PSDIS: length 72.9
  TOP w0.381: UT27.13 156.4,23.15 154.7,21.45 v1(154.7,15.91)
  LAYER3 w0.381: v1(154.7,15.91) 125.29,15.91 124.12,17.08 119.53,17.08 112.77,10.32 100.21,10.32 JB8.11
X-PSDIS-OUT: length 18.7
  TOP w0.381: JT26.145 167.5,43.26 157.05,32.81 UT27.7
X-RTD: length 117
  TOP w0.381: UT35.5 101.87,19.81 101.88,19.8 102.14,19.8 v1(102.58,19.36) ; v1(86.57,73.12) 82.52,69.07 v1(82.52,61.71) ; v1(110.83,29.5) 116.14,34.81 116.14,35.82 123.95,43.63 124.23,43.63 124.84,44.24 JT26.89
  LAYER3 w0.381: v1(77.3,38.46) 77.3,36.98 77.91,36.37 77.91,33.95 88.88,22.97 96.33,22.97 99.94,19.36 v1(102.58,19.36) 104.71,21.49 104.71,22.89 109.29,27.48 109.29,27.96 v1(110.83,29.5)
  BOTTOM w0.254: RB50.1 85.21,73.82 84.51,74.52 84.51,75.72 84.9,76.11 UB9.2
  BOTTOM w0.381: RB50.1 86.05,73.64 v1(86.57,73.12) ; v1(82.52,61.71) 77.3,56.5 v1(77.3,38.46)
X-RTD-N: length 32.8
  TOP w0.381: JB8.10 95.37,5.49 95.37,7.41 96.78,8.82 106.64,8.82 110.51,12.69 110.51,20.39 108.5,22.41 LT16.1
X-RTD-N-FILTER: length 5.5
  TOP w0.381: RT204.2 102.65,22.32 101.98,21.64 101.98,21.59 101.5,21.11 UT35.7
  TOP w0.508: LT16.2 104.19,22.41 CT135.2 RT204.2
X-RTD-P: length 28.9
  TOP w0.381: JB8.9 94.11,6.94 96.55,9.38 106.41,9.38 109.95,12.92 109.95,20.16 109.18,20.94 108.34,20.94 108.04,20.63 LT19.1
X-RTD-P-FILTER: length 5
  TOP w0.381: UT35.6 102.45,20.46 RT204.1
  TOP w0.508: RT204.1 CT135.1 104.19,20.63 LT19.2
X-TEMP: length 24
  TOP w0.381: v1(99.23,44.39) 99.24,44.4 JT26.33
  BOTTOM w0.381: v1(99.23,44.39) 99.23,45.02 101.53,47.31 101.53,53.05 101.18,53.4 101.18,54.87 95.98,60.07 CB51.1 RB69.2
XHS-PWM: length 27.2
  TOP w0.381: JT26.54 v1(107.24,48.78)
  TOP w0.508: RT190.1 v1(105.04,24.91)
  BOTTOM w0.381: JT36.1 107.4,39.47 107.24,39.63 v1(107.24,48.78)
  BOTTOM w0.508: JT36.1 107.4,35.73 107.54,35.59 107.54,27.41 v1(105.04,24.91)
XHS-PWM-N: length 36.9
  TOP w0.381: UT25.3 101.59,27.96 101.8,28.17 102.26,28.17 102.31,28.22 102.68,28.22 v1(102.68,28.5)
  BOTTOM w0.381: JB8.4 86.49,4.99 85.24,6.25 85.24,14.69 94.42,23.87 98.55,23.87 102.68,28.01 v1(102.68,28.5)
XHS-PWM-P: length 34.3
  TOP w0.381: v1(103.57,27.61) 102.03,27.61 101.73,27.31 UT25.2
  BOTTOM w0.381: JB8.3 86.49,7.47 85.8,8.17 85.8,14.45 94.66,23.31 98.78,23.31 103.08,27.61 v1(103.57,27.61)
XLS-PWM: length 28.9
  TOP w0.381: JT26.56 v1(108.03,48.78)
  TOP w0.508: JT37.1 113.5,34.73 112.91,34.15 105.86,34.15 104.74,33.02 RT168.1
  BOTTOM w0.381: JT37.1 113.5,38.32 112.52,39.3 110.55,39.3 108.03,41.83 v1(108.03,48.78)
XLS-PWM-N: length 39.3
  TOP w0.381: UT25.5 102.02,29.26 102.16,29.4 103.4,29.4 v1(103.58,29.21)
  BOTTOM w0.381: v1(103.58,29.21) 104.49,28.31 104.49,27.12 103.64,26.27 103.64,23.73 100.72,20.81 100.72,15.6 98.94,13.83 93.23,13.83 87.75,8.35 87.75,5.51 JB8.6
XLS-PWM-P: length 38.3
  TOP w0.381: v1(104.47,30.1) 104.32,29.95 100.61,29.95 UT25.6
  BOTTOM w0.381: JB8.5 88.31,7.49 88.31,8.12 93.46,13.27 99.17,13.27 101.28,15.37 101.28,20.58 104.2,23.5 104.2,26.04 105.05,26.89 105.05,28.54 104.26,29.33 104.26,29.73 104.47,29.94 v1(104.47,30.1)
Y-FAULT: length 86.7
  TOP w0.381: UT35.11 93.77,20.46 v1(93.3,19.99) ; JT26.123 158.71,44.47 158.73,44.45 v1(158.73,43.82) 158.73,43.2 158.69,43.16 158.69,41.11 v1(152.76,35.18)
  LAYER3 w0.381: v1(152.76,35.18) 150.08,32.49 118.73,32.49 111.49,25.25 111.49,22.46 106.46,17.43 94.13,17.43 93.31,18.25 v1(93.3,19.99)
  BOTTOM w0.381: v1(158.73,43.82) 158.72,43.81 158.72,43.27 159.06,42.93 UB20.3
Y-FAULT-N: length 40.3
  TOP w0.381: LT14.1 87.84,23.17 84.05,19.38 84.05,15.98 80.62,12.56 65.29,12.56 60.47,7.74 60.47,6.47 60.46,6.46 60.46,5.5 JB7.8
Y-FAULT-N-FILTER: length 5.4
  TOP w0.381: UT35.9 94.32,21.76 93.94,22.15 93.91,22.15 92.97,23.08 RT196.2
  TOP w0.508: RT196.2 CT132.2 90.22,23.08 LT14.2
Y-FAULT-P: length 35.5
  TOP w0.381: JB7.7 61.73,8.21 65.52,12 80.86,12 84.61,15.75 84.61,19.15 86.85,21.39 LT17.1
Y-FAULT-P-FILTER: length 5
  TOP w0.381: RT196.1 93.18,21.23 93.61,21.23 93.73,21.11 UT35.10
  TOP w0.508: LT17.2 90.22,21.48 CT132.1 RT196.1
Y-LEN: length 100.6
  TOP w0.381: v1(156.05,17.26) 156.05,20.79 157.7,22.44 UT27.15
  LAYER3 w0.381: JB7.13 74.25,11.67 112.22,11.67 118.74,18.19 124.58,18.19 125.52,17.26 v1(156.05,17.26)
Y-LEN-OUT: length 19.2
  TOP w0.381: UT27.5 158.35,32.46 169.92,44.02 JT26.151
Y-OCEN: length 97.9
  TOP w0.381: v1(155.37,16.58) 155.37,21.11 157.05,22.78 UT27.14
  LAYER3 w0.381: JB7.15 76.11,10.99 112.5,10.99 119.14,17.64 124.35,17.64 125.41,16.58 v1(155.37,16.58)
Y-OCEN-OUT: length 19.1
  TOP w0.381: UT27.6 157.7,32.67 169.1,44.07 JT26.149
Y-PSDIS: length 104.2
  TOP w0.381: v1(156.72,17.93) 156.72,20.55 158.35,22.18 UT27.16
  LAYER3 w0.381: v1(156.72,17.93) 125.64,17.93 123.8,19.77 117.5,19.77 110.07,12.34 72.38,12.34 JB7.11
Y-PSDIS-OUT: length 19.3
  TOP w0.381: JT26.153 170.7,44.02 159,32.32 UT27.4
Y-RTD: length 131.8
  TOP w0.381: v1(111.39,28.94) 116.93,34.48 116.93,35.5 124.5,43.07 124.51,43.07 125.63,44.19 JT26.91 ; v1(92.03,19.74) 92.61,19.16 UT35.13 ; v1(96.4,72.86) 95.87,73.39 90.32,73.39 83.19,66.26 83.19,61.43 83.17,61.41 v1(83.17,61.19)
  LAYER3 w0.381: v1(111.39,28.94) 110.08,27.64 110.08,26.36 106.06,22.34 106.06,19.16 105.12,18.22 96.83,18.22 94.24,20.81 93.1,20.81 v1(92.03,19.74) 90.79,19.74 77.13,33.4 77.13,35.51 v1(76.29,36.36)
  BOTTOM w0.254: UB10.2 94.82,76.11 94.43,75.72 94.43,74.52 95.13,73.82 RB51.1
  BOTTOM w0.381: RB51.1 95.92,72.86 v1(96.4,72.86) ; v1(76.29,36.36) 78.29,38.36 78.29,56.32 v1(83.17,61.19)
Y-RTD-N: length 30.8
  TOP w0.381: JB7.10 65.53,5.49 65.53,8.45 67.3,10.22 80.86,10.22 87.2,16.57 LT24.1
Y-RTD-N-FILTER: length 5.5
  TOP w0.381: RT215.2 92.85,16.65 93.52,17.33 93.52,17.38 94,17.86 UT35.15
  TOP w0.508: LT24.2 90.09,16.65 CT143.2 RT215.2
Y-RTD-P: length 29.5
  TOP w0.381: LT21.1 88.09,18.34 80.53,10.78 67.07,10.78 64.65,8.36 64.65,7.15 JB7.9
Y-RTD-P-FILTER: length 5
  TOP w0.381: UT35.14 93.62,18.51 93.36,18.25 RT215.1
  TOP w0.508: LT21.2 90.09,18.25 CT143.1 RT215.1
Y-TEMP: length 22.5
  TOP w0.381: JT26.37 100.84,44.4 v1(100.83,44.39)
  BOTTOM w0.381: RB70.2 CB52.1 99.24,57.67 101.78,55.12 101.78,53.65 102.13,53.3 102.13,46.68 100.83,45.38 v1(100.83,44.39)
YHS-PWM: length 28.3
  TOP w0.381: JT26.57 112.04,44.51 110.23,42.71 v1(106.23,42.71)
  TOP w0.508: JT34.1 93.61,36.81 91.5,34.7 RT167.1
  BOTTOM w0.381: v1(106.23,42.71) 104.2,42.71 101.99,40.5 97.39,40.5 95.21,38.32 JT34.1
YHS-PWM-N: length 53.7
  TOP w0.381: UT25.11 94.84,29.95 94.28,29.95 94.25,29.91 90.42,29.91 82.36,21.85 82.36,17.79 79.31,14.74 63.08,14.74 57.91,9.57 57.91,5.49 JB7.4
YHS-PWM-P: length 51.8
  TOP w0.381: JB7.3 56.65,9.1 62.85,15.3 79.08,15.3 81.8,18.02 81.8,22.08 90.19,30.47 94.01,30.47 94.05,30.5 94.84,30.5 94.87,30.53 UT25.10
YLS-PWM: length 37.6
  TOP w0.381: v1(106.26,41.87) 110.27,41.87 112.83,44.42 JT26.59
  TOP w0.508: RT185.1 90.21,25.34 90.04,25.51 v1(89.42,25.51)
  BOTTOM w0.381: JT35.1 101.31,39.02 104.16,41.87 v1(106.26,41.87)
  BOTTOM w0.508: JT35.1 101.31,34.23 100.21,33.13 96.78,33.13 89.86,26.2 89.86,25.95 v1(89.42,25.51)
YLS-PWM-N: length 51.9
  TOP w0.381: v1(59.06,8.75) 64.34,14.02 79.83,14.02 82.94,17.12 82.94,21.19 90.27,28.52 94.01,28.52 94.05,28.55 94.84,28.55 94.87,28.58 UT25.13
  BOTTOM w0.381: v1(59.06,8.75) 57.93,7.61 57.93,5.49 JB7.6
YLS-PWM-P: length 47.6
  TOP w0.381: UT25.14 94.84,27.99 94.28,27.99 94.25,27.96 90.5,27.96 83.49,20.96 83.49,16.89 80.07,13.46 64.57,13.46 59.9,8.79 59.9,7.48 JB7.5
Z-FAULT: length 111.8
  TOP w0.381: v1(153.32,34.63) 156.61,37.92 156.72,37.92 v1(157.34,38.54) 157.34,38.64 159.5,40.81 JT26.125 ; v1(70.34,19.92) 70.93,20.52 UT34.3
  LAYER3 w0.381: v1(153.32,34.63) 150.4,31.71 119.06,31.71 112.28,24.93 112.28,22.14 106.86,16.72 93.72,16.72 93.01,17.43 72.59,17.67 v1(70.34,19.92)
  BOTTOM w0.381: UB20.6 157.16,39.61 157.34,39.43 v1(157.34,38.54)
Z-FAULT-N: length 46.5
  TOP w0.381: LT15.1 66.4,22.59 63.76,22.59 53.52,12.34 35.61,12.34 30.63,7.36 30.63,5.49 JB6.8
Z-FAULT-N-FILTER: length 5.4
  TOP w0.381: RT197.2 71.53,23.01 72.34,22.2 72.63,22.2 73.01,21.82 UT34.1
  TOP w0.508: LT15.2 70,23.1 CT133.2 RT197.2
Z-FAULT-P: length 42.4
  TOP w0.381: LT18.1 66.91,21.63 66.6,21.93 66.57,21.93 66.54,21.97 66.31,21.97 66.25,22.03 63.99,22.03 53.75,11.78 35.84,11.78 32.74,8.68 32.74,7.62 JB6.7
Z-FAULT-P-FILTER: length 5
  TOP w0.381: UT34.2 72.49,21.17 72.24,21.41 RT197.1
  TOP w0.508: LT18.2 70,21.32 CT133.1 RT197.1
Z-LEN: length 138.5
  TOP w0.381: UT28.17 167,23.65 164.16,20.81 159.27,20.81 158.82,20.36 v1(158.82,19.21)
  LAYER3 w0.381: JB6.13 46.32,13.59 109.45,13.59 117.06,21.19 156.84,21.19 v1(158.82,19.21)
Z-LEN-OUT: length 17
  TOP w0.381: JT26.161 173.9,43.87 167.65,37.61 UT28.3
Z-OCEN: length 135.5
  TOP w0.381: UT28.16 166.35,24.19 163.6,21.45 159.01,21.45 158.15,20.58 v1(158.15,18.54)
  LAYER3 w0.381: JB6.15 48.19,12.91 109.73,12.91 117.31,20.49 156.19,20.49 v1(158.15,18.54)
Z-OCEN-OUT: length 16.9
  TOP w0.381: JT26.159 173.12,43.87 167,37.76 UT28.4
Z-PSDIS: length 141.3
  TOP w0.381: v1(159.49,19.88) 164.31,19.88 167.65,23.22 UT28.18
  LAYER3 w0.381: JB6.11 44.4,14.2 109.2,14.2 116.85,21.85 157.53,21.85 v1(159.49,19.88)
Z-PSDIS-OUT: length 17.1
  TOP w0.381: JT26.163 174.72,43.89 168.3,37.47 UT28.2
Z-RTD: length 153.2
  TOP w0.381: v1(83.97,60.6) 83.97,65.22 88.8,70.05 88.89,70.05 90.57,71.74 98.85,71.74 99.39,71.2 105.08,71.2 v1(106.51,72.63) ; v1(71.86,19.67) 72.3,19.23 72.43,19.23 72.44,19.22 UT34.5 ; JT26.93 126.44,43.86 117.74,35.16 117.74,34.15 v1(112.66,29.07)
  LAYER3 w0.381: v1(112.66,29.07) 110.88,30.84 89.04,30.84 v1(85.86,27.67)
  BOTTOM w0.254: RB52.1 105.05,73.82 104.35,74.52 104.35,75.72 104.74,76.11 UB11.2
  BOTTOM w0.381: RB52.1 106.07,72.63 v1(106.51,72.63) ; v1(85.86,27.67) 85.42,27.23 85.42,26.94 78.4,19.92 76.84,19.92 75.83,18.91 72.62,18.91 v1(71.86,19.67) 71.86,30.36 79.46,37.96 79.46,56.09 v1(83.97,60.6)
Z-RTD-N: length 40.5
  TOP w0.381: JB6.10 35.68,5.49 35.68,9.08 37.26,10.67 54.29,10.67 61.23,17.61 65.83,17.61 66.81,16.62 LT23.1
